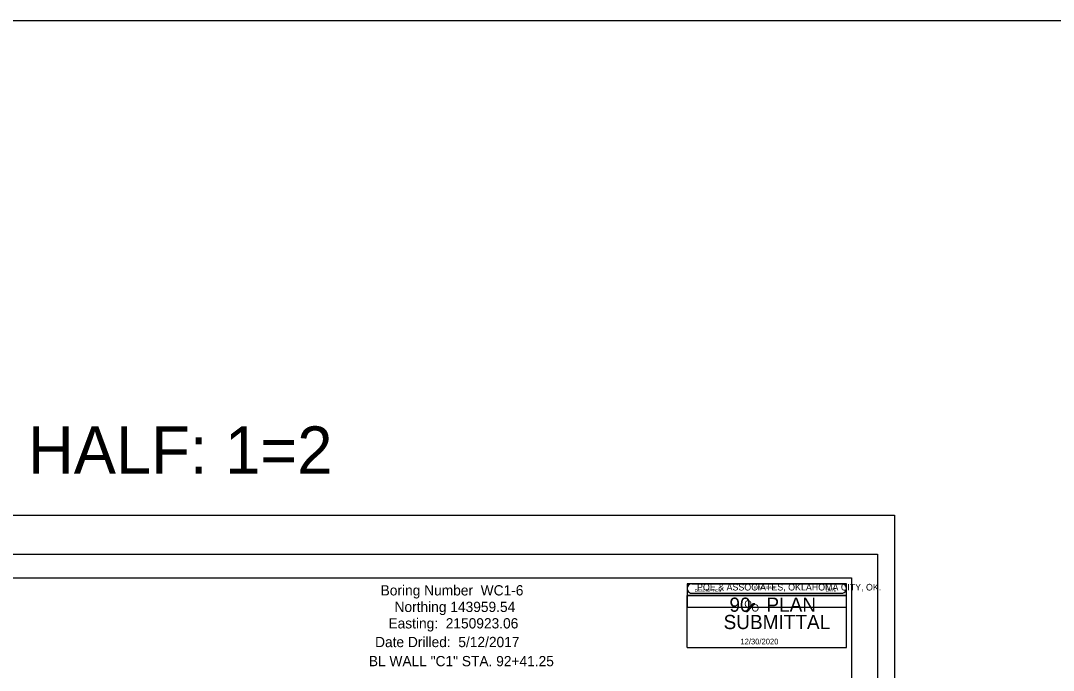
# Model space of a CAD drawing. Extents: x -6 to 173, y 24 to 64.
# Drawn here: x 107.52 to 129.33, y 50.69 to 64.42 of the extents above; entities that cross this region are included whole.
import ezdxf

# ---------------------------------------------------------------- set-up
doc = ezdxf.new("R2010")
doc.units = 0
for name, color, linetype in [('S', 7, 'Continuous'), ('SHT_Plot_Shape_Full', 7, 'Continuous'), ('SHT_Plot_Shape_Half', 7, 'Continuous'), ('SHT_Sheet_Border', 7, 'Continuous'), ('SHT_Stamp_90_Submit', 7, 'Continuous'), ('SHT_Stamp_Rev_Block', 7, 'Continuous')]:
    doc.layers.add(name, color=color, linetype=linetype)

msp = doc.modelspace()

# ---------------------------------------------------------------- linework, layer by layer
at = {"layer": 'S'}
msp.add_lwpolyline([(-6.024, 64.421), (172.576, 64.421), (172.576, 25.783), (-6.024, 25.783)], close=True, dxfattribs=at)
at = {"layer": 'SHT_Plot_Shape_Full'}
msp.add_lwpolyline([(89.979, 53.971), (125.979, 53.971), (125.979, 29.971), (89.979, 29.971)], close=True, dxfattribs=at)
at = {"layer": 'SHT_Plot_Shape_Half'}
msp.add_lwpolyline([(91.616, 53.146), (125.616, 53.146), (125.616, 31.146), (91.616, 31.146)], close=True, dxfattribs=at)
at = {"layer": 'SHT_Sheet_Border'}
msp.add_lwpolyline([(93.566, 52.646), (125.066, 52.646), (125.066, 31.646), (93.566, 31.646)], close=True, dxfattribs=at)
at = {"layer": 'SHT_Stamp_90_Submit'}
for p, q in [((121.697, 52.522), (124.863, 52.522)), ((121.597, 52.272), (124.963, 52.272)), ((121.597, 51.173), (121.597, 52.272)), ((121.697, 52.322), (124.863, 52.322)), ((124.963, 51.173), (124.963, 52.272)), ((122.84, 51.934), (122.996, 52.107)), ((122.84, 51.934), (122.871, 51.934)), ((122.858, 51.934), (123.014, 52.107)), ((122.863, 51.934), (123.019, 52.107)), ((122.871, 51.934), (123.027, 52.107)), ((122.996, 52.107), (123.027, 52.107)), ((121.597, 51.173), (124.963, 51.173))]:
    msp.add_line(p, q, dxfattribs=at)
for centre, start, end in [((121.698, 52.422), 89.9952, 270), ((124.863, 52.422), 270, 90.0048)]:
    msp.add_arc(centre, 0.1, start, end, dxfattribs=at)
at = {"layer": 'SHT_Stamp_Rev_Block'}
for p, q in [((121.598, 52.522), (121.598, 52.022)), ((124.963, 52.522), (121.598, 52.522)), ((124.963, 52.022), (124.963, 52.522)), ((124.963, 52.272), (121.598, 52.272)), ((124.963, 52.022), (121.598, 52.022))]:
    msp.add_line(p, q, dxfattribs=at)

# ---------------------------------------------------------------- texts
for s, p in [('Boring Number  WC1-6', (115.126, 52.275)), ('Northing 143959.54', (115.42, 51.925)), ('Easting:  2150923.06', (115.291, 51.578)), ('Date Drilled:  5/12/2017', (115.009, 51.183)), ('BL WALL "C1" STA. 92+41.25', (114.877, 50.779))]:
    msp.add_text(s, height=0.217).set_placement(p)
at = {"layer": 'S'}
msp.add_text('FULL: 1=1   HALF: 1=2', height=1, dxfattribs=at).set_placement((100.284, 54.847))
at = {"layer": 'SHT_Stamp_90_Submit'}
for s, height, p in [('POE & ASSOCIATES, OKLAHOMA CITY, OK.', 0.14, (121.807, 52.38)), ('90   PLAN', 0.3, (122.492, 51.93)), ('O', 0.153, (122.806, 52.019)), ('O', 0.153, (122.958, 51.935)), ('SUBMITTAL', 0.3, (122.368, 51.564)), ('12/30/2020', 0.12, (122.723, 51.241))]:
    msp.add_text(s, height=height, dxfattribs=at).set_placement(p)
at = {"layer": 'SHT_Stamp_Rev_Block'}
for s, height, p in [('DESCRIPTION', 0.05999, (121.757, 52.351)), ('REVISIONS', 0.06, (123.006, 52.41)), ('DATE', 0.06, (124.527, 52.355))]:
    msp.add_text(s, height=height, dxfattribs=at).set_placement(p)

doc.saveas('drawing.dxf')
